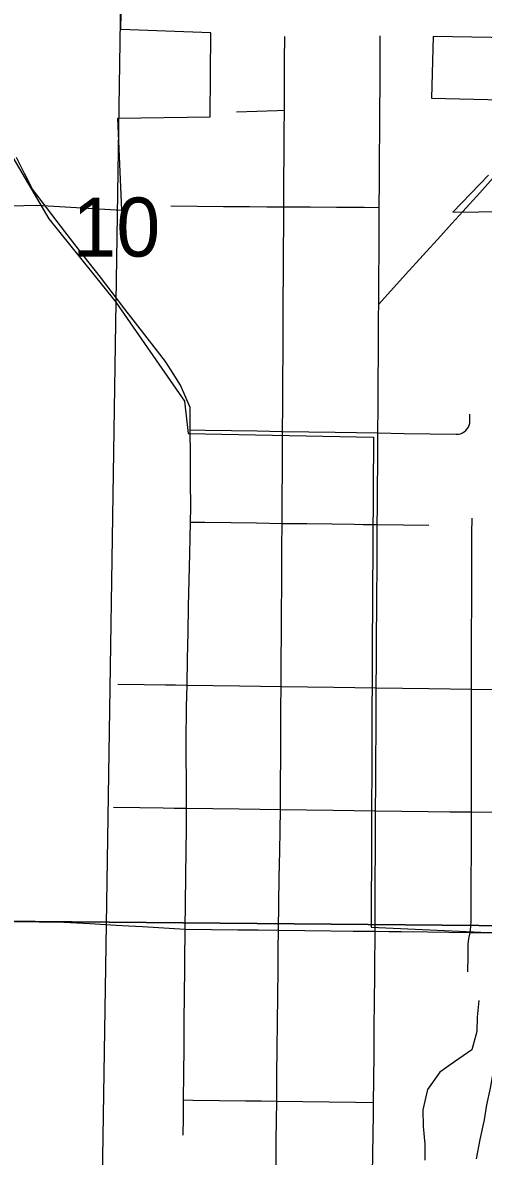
# Model space of a CAD drawing. Extents: x -11.1 to 34, y -3.9 to 22.
# Drawn here: x 4.812 to 5.139, y 16.102 to 16.906 of the extents above; entities that cross this region are included whole.
import ezdxf

# ---------------------------------------------------------------- set-up
doc = ezdxf.new("R2010")
doc.units = 0
for name, color, linetype in [('GM_X_City_Street', 7, 'Continuous'), ('GM_X_Corporation', 7, 'Continuous'), ('GM_X_County_Road', 7, 'Continuous'), ('GM_X_Minor_River', 7, 'Continuous'), ('GM_X_Rail_Line', 7, 'Continuous'), ('GM_X_Section_Text', 7, 'Continuous'), ('GM_X_State_Route', 7, 'Continuous')]:
    doc.layers.add(name, color=color, linetype=linetype)

msp = doc.modelspace()

# ---------------------------------------------------------------- linework, layer by layer
at = {"layer": 'GM_X_City_Street'}
for points in [[(4.99717, 16.77555), (4.99727, 16.79419), (4.99737, 16.81283), (4.99746, 16.82842), (4.99755, 16.844), (4.99765, 16.86264), (4.99774, 16.87948), (4.99783, 16.89631)], [(5.06439, 16.6976), (5.06445, 16.70644), (5.06457, 16.72508), (5.06469, 16.74372), (5.06479, 16.75941), (5.06488, 16.77509), (5.06499, 16.79373), (5.0651, 16.81237), (5.06519, 16.82797), (5.06528, 16.84357), (5.06539, 16.86221), (5.06549, 16.87946), (5.06559, 16.8967)], [(4.9637, 16.84294), (4.97804, 16.84335), (4.99237, 16.84375), (4.99755, 16.844)], [(4.917, 16.77613), (4.93565, 16.77599), (4.95429, 16.77585), (4.97293, 16.77572), (4.98504, 16.77564), (4.99717, 16.77555), (5.01581, 16.77543), (5.03445, 16.7753), (5.04434, 16.77523), (5.05422, 16.77517), (5.06488, 16.77509)], [(4.99332, 16.26255), (4.99363, 16.28119), (4.99393, 16.29984), (4.99423, 16.31848), (4.99448, 16.33333), (4.99472, 16.34818), (4.99483, 16.36683), (4.99494, 16.38547), (4.99505, 16.40411), (4.99515, 16.41975), (4.99525, 16.4354), (4.99536, 16.45404), (4.99547, 16.47268), (4.99558, 16.49132), (4.99565, 16.50413), (4.99573, 16.51694), (4.99583, 16.53401), (4.99593, 16.55107), (4.99604, 16.56972), (4.99615, 16.58836), (4.99624, 16.60233), (4.99632, 16.6163), (4.99642, 16.63494), (4.99652, 16.65358), (4.99661, 16.67222), (4.99671, 16.69086), (4.99681, 16.7095), (4.99691, 16.72815), (4.99701, 16.74679), (4.99709, 16.76117), (4.99717, 16.77555)], [(5.06192, 16.26175), (5.06199, 16.28039), (5.06206, 16.29903), (5.06213, 16.31767), (5.06224, 16.34717), (5.06235, 16.36581), (5.06246, 16.38445), (5.06257, 16.40309), (5.06267, 16.41877), (5.06277, 16.43446), (5.06288, 16.4531), (5.06299, 16.47174), (5.06311, 16.49038), (5.06318, 16.50322), (5.06326, 16.51606), (5.06333, 16.52657), (5.0634, 16.53709), (5.06348, 16.55015), (5.06355, 16.56282), (5.06364, 16.57548), (5.06375, 16.59412), (5.06382, 16.60462), (5.06388, 16.61514), (5.064, 16.63378), (5.06411, 16.65242), (5.06423, 16.67106), (5.06434, 16.68875), (5.06439, 16.6976)], [(4.93084, 16.61742), (4.94147, 16.61724), (4.96012, 16.61692), (4.97822, 16.61661), (4.99632, 16.6163), (5.01496, 16.61598), (5.0336, 16.61566), (5.04874, 16.6154), (5.06388, 16.61514), (5.08252, 16.61482), (5.10102, 16.6145), (5.11952, 16.61419), (5.12102, 16.61428), (5.12249, 16.61461), (5.12388, 16.61517), (5.12517, 16.61595), (5.12632, 16.61691), (5.12731, 16.61805), (5.1281, 16.61933), (5.12867, 16.62071), (5.12903, 16.62217), (5.12915, 16.62367), (5.12914, 16.62858)], [(4.92716, 16.26336), (4.9274, 16.282), (4.92764, 16.30064), (4.92787, 16.31928), (4.92807, 16.33418), (4.92825, 16.34907), (4.92813, 16.36771), (4.92802, 16.38636), (4.92795, 16.39587), (4.92821, 16.42086), (4.92852, 16.43633), (4.92891, 16.45497), (4.92929, 16.4736), (4.92967, 16.49224), (4.93005, 16.51087), (4.93044, 16.52951), (4.93067, 16.54074), (4.9309, 16.55197), (4.93111, 16.56241), (4.93102, 16.58105), (4.93093, 16.59924), (4.93084, 16.61742)], [(5.12923, 16.26095), (5.12973, 16.26518), (5.12999, 16.26946), (5.13017, 16.3464), (5.13025, 16.43351), (5.13051, 16.53359), (5.13063, 16.54417), (5.13073, 16.55475)], [(4.9309, 16.55197), (4.94113, 16.55183), (4.95977, 16.55157), (4.97785, 16.55132), (4.99593, 16.55107), (5.01355, 16.55084), (5.03118, 16.5506), (5.04732, 16.55038), (5.05338, 16.55029)], [(5.05338, 16.55029), (5.06348, 16.55015), (5.08206, 16.5499), (5.0999, 16.54966)], [(4.87955, 16.43702), (4.89819, 16.43676), (4.91336, 16.43654), (4.92044, 16.43644)], [(4.92044, 16.43644), (4.92852, 16.43633), (4.94717, 16.43607), (4.96581, 16.43581), (4.98053, 16.43561), (4.99525, 16.4354), (5.01389, 16.43514), (5.03253, 16.43488), (5.04765, 16.43467), (5.06277, 16.43446), (5.08141, 16.43419), (5.10005, 16.43393), (5.11515, 16.43372), (5.13025, 16.43351), (5.14889, 16.43328), (5.16305, 16.43311), (5.1772, 16.43294)], [(4.87644, 16.34978), (4.89508, 16.34952), (4.91167, 16.3493), (4.91947, 16.34919)], [(4.91947, 16.34919), (4.92825, 16.34907), (4.94689, 16.34882), (4.96553, 16.34858), (4.98013, 16.34838), (4.99472, 16.34818), (5.01336, 16.3479), (5.032, 16.34763), (5.04712, 16.3474), (5.06224, 16.34717), (5.08088, 16.34695), (5.09952, 16.34674), (5.11485, 16.34657), (5.13017, 16.3464), (5.14881, 16.34616), (5.16638, 16.34594), (5.18395, 16.34571)], [(4.92584, 16.11712), (4.92596, 16.12962), (4.92607, 16.14213), (4.92624, 16.16077), (4.92641, 16.17941), (4.92657, 16.19805), (4.92674, 16.21669), (4.92691, 16.23533), (4.92701, 16.24649), (4.92711, 16.25765), (4.92716, 16.26336)], [(5.05932, 16.04538), (5.05962, 16.06402), (5.05991, 16.08266), (5.06021, 16.1013), (5.06051, 16.11994), (5.06067, 16.13014), (5.06084, 16.14034), (5.06098, 16.15615), (5.06115, 16.17479), (5.06132, 16.19343), (5.06148, 16.21207), (5.06165, 16.23071), (5.06175, 16.24245), (5.06185, 16.2542), (5.06192, 16.26175)], [(5.12764, 16.23292), (5.12781, 16.24453), (5.12793, 16.25275), (5.12828, 16.25636), (5.12923, 16.26095)], [(4.92607, 16.14213), (4.93266, 16.14205), (4.9513, 16.1418), (4.96995, 16.14155), (4.98103, 16.14141), (4.99212, 16.14126), (5.01076, 16.14101), (5.02937, 16.14076), (5.04798, 16.14051), (5.06084, 16.14034)]]:
    msp.add_lwpolyline(points, dxfattribs=at)
at = {"layer": 'GM_X_Corporation'}
for points in [[(5.38498, 17.2762), (5.37154, 16.26384), (4.37464, 16.27278), (4.38657, 17.28555)], [(4.37464, 16.27278), (5.37154, 16.26384), (5.35589, 15.25381), (4.35794, 15.26693)]]:
    msp.add_lwpolyline(points, close=True, dxfattribs=at)
for points in [[(4.75642, 16.77507), (4.8221, 16.77674), (4.88228, 16.77318), (4.87945, 16.83835), (4.94487, 16.83927), (4.94546, 16.89896), (4.88168, 16.90139), (4.88285, 16.9607)], [(5.1716, 16.8951), (5.10312, 16.89638), (5.10184, 16.85264), (5.19203, 16.85035)], [(5.14222, 16.79795), (5.11699, 16.77165), (5.20879, 16.77292)]]:
    msp.add_lwpolyline(points, dxfattribs=at)
at = {"layer": 'GM_X_County_Road'}
msp.add_line((5.1189, 16.76649), (5.12408, 16.7722), dxfattribs=at)
for points in [[(4.82876, 16.77515), (4.81886, 16.78806), (4.81325, 16.79925), (4.80765, 16.81043)], [(5.12408, 16.7722), (5.13609, 16.78544), (5.14758, 16.7981)], [(4.93084, 16.61742), (4.93076, 16.63323), (4.92396, 16.64896), (4.91859, 16.65737), (4.91323, 16.66577), (4.90184, 16.68053), (4.89044, 16.69528), (4.88445, 16.70304), (4.87847, 16.71079), (4.86707, 16.72554), (4.85568, 16.74029), (4.84429, 16.75505), (4.83652, 16.7651), (4.82876, 16.77515)], [(5.06445, 16.70644), (5.07098, 16.71364), (5.0835, 16.72744), (5.09602, 16.74125), (5.10854, 16.75506), (5.11631, 16.76363), (5.1189, 16.76649)], [(4.99165, 16.09507), (4.99184, 16.11371), (4.99198, 16.12749), (4.99212, 16.14126), (4.9923, 16.1599), (4.99249, 16.17854), (4.99268, 16.19719), (4.99286, 16.21583), (4.99305, 16.23447), (4.99318, 16.24851), (4.99332, 16.26255)]]:
    msp.add_lwpolyline(points, dxfattribs=at)
at = {"layer": 'GM_X_Minor_River'}
for points in [[(5.16142, 16.27639), (5.15924, 16.2635), (5.15858, 16.25057), (5.15642, 16.23844), (5.15388, 16.22633), (5.15128, 16.21116), (5.14991, 16.20054), (5.14927, 16.18837), (5.14827, 16.17736), (5.14567, 16.16258), (5.14351, 16.15045), (5.14098, 16.13871), (5.13923, 16.12809), (5.13627, 16.11408), (5.1337, 16.10044)], [(5.13538, 16.21267), (5.13436, 16.2009), (5.13414, 16.19063), (5.13045, 16.17777), (5.11813, 16.1693), (5.10773, 16.16194), (5.09911, 16.14958), (5.09576, 16.13519), (5.09589, 16.12339), (5.09713, 16.11081), (5.09726, 16.09938)]]:
    msp.add_lwpolyline(points, dxfattribs=at)
at = {"layer": 'GM_X_Rail_Line'}
msp.add_line((4.87729, 16.70888), (4.87801, 16.70783), dxfattribs=at)
for points in [[(4.83755, 14.09996), (4.84005, 14.24738), (4.85562, 15.25898), (4.87136, 16.26658), (4.87826, 16.70806), (4.89599, 17.85935), (4.89412, 17.93146), (4.88952, 17.98439), (4.8767, 18.04189), (4.68365, 18.67523), (4.66078, 18.75097), (4.64705, 18.79843), (4.63971, 18.85502), (4.64675, 19.28767), (4.67685, 20.63104), (4.68041, 20.82286), (4.68184, 20.89996)], [(4.39761, 18.24957), (4.39332, 17.85981), (4.61396, 17.28052), (4.65288, 17.10434), (4.80336, 16.81332), (4.83062, 16.76705), (4.87729, 16.70888)], [(4.87801, 16.70783), (4.92664, 16.63771), (4.92939, 16.61489), (5.06087, 16.61224), (5.05979, 16.4614), (5.05905, 16.26479), (5.18891, 16.25889), (5.22866, 15.82439), (5.27609, 15.27216), (5.27847, 15.2153), (5.26663, 14.92751), (5.27495, 14.79199), (5.30526, 14.66939), (5.32778, 14.63192)]]:
    msp.add_lwpolyline(points, dxfattribs=at)
at = {"layer": 'GM_X_State_Route'}
for points in [[(4.59707, 16.27182), (4.60099, 16.27176), (4.61964, 16.27149), (4.63828, 16.27122), (4.65692, 16.27094), (4.67556, 16.27067), (4.6942, 16.2704), (4.71284, 16.27012), (4.73148, 16.26985), (4.75012, 16.26958), (4.76876, 16.2693), (4.78741, 16.26903), (4.80605, 16.26875), (4.82356, 16.2685), (4.84107, 16.26825), (4.85968, 16.26719), (4.87829, 16.26613), (4.88711, 16.26563)], [(4.88711, 16.26563), (4.8969, 16.26508), (4.91203, 16.26422), (4.92716, 16.26336), (4.94581, 16.26313), (4.96445, 16.26291), (4.97889, 16.26273), (4.99332, 16.26255)], [(4.99332, 16.26255), (5.01196, 16.26234), (5.0306, 16.26212), (5.04626, 16.26193), (5.06192, 16.26175), (5.07173, 16.26163)], [(5.07173, 16.26163), (5.08056, 16.26153), (5.0992, 16.2613), (5.11422, 16.26113), (5.12923, 16.26095), (5.15233, 16.261)]]:
    msp.add_lwpolyline(points, dxfattribs=at)

# ---------------------------------------------------------------- texts
at = {"layer": 'GM_X_Section_Text'}
msp.add_text('10', height=0.041856, rotation=0.00001, dxfattribs=at).set_placement((4.84727, 16.74024))

doc.saveas('drawing.dxf')
